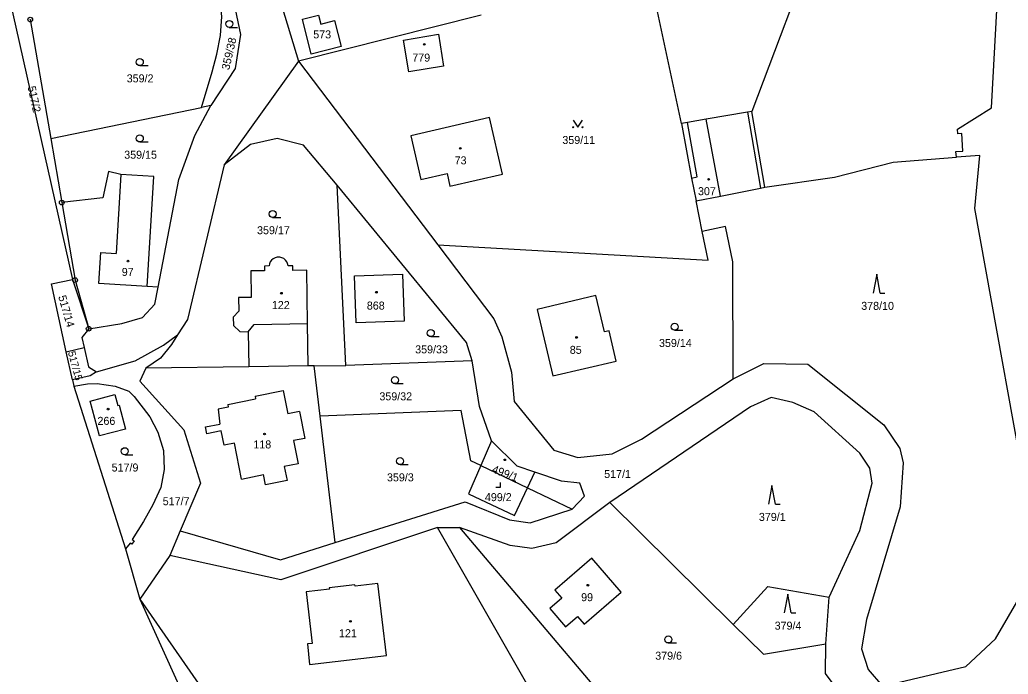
# Model space of a CAD drawing. Extents: x -725728 to -720881, y -1068679 to -1063504.
# Drawn here: x -723846.7 to -723636.7, y -1067162.6 to -1067023.6 of the extents above; entities that cross this region are included whole.
import ezdxf

# ---------------------------------------------------------------- set-up
doc = ezdxf.new("R2010")
doc.units = 0
for name, color, linetype in [('Hranice parcel', 7, 'Continuous'), ('Parcelní čísla', 7, 'Continuous'), ('Vnitřní kresba', 7, 'Continuous'), ('Značky bodu BP', 7, 'Continuous'), ('Značky budov', 7, 'Continuous'), ('Značky kultur', 7, 'Continuous')]:
    doc.layers.add(name, color=color, linetype=linetype)

# ---------------------------------------------------------------- blocks, each defined once
blk = doc.blocks.new('4.02_3')
at = {"layer": 'Značky budov'}
blk.add_circle((-0.001, 0), 0.0175, dxfattribs=at)
blk = doc.blocks.new('4.02_4')
at = {"layer": 'Značky budov'}
blk.add_circle((-0.001, 0), 0.0175, dxfattribs=at)
blk = doc.blocks.new('3.04_2')
at = {"layer": 'Značky kultur'}
blk.add_line((0.001, 0), (0.176, 0), dxfattribs=at)
blk.add_circle((0.001, 0.075), 0.075, dxfattribs=at)
blk = doc.blocks.new('3.14_1')
at = {"layer": 'Značky kultur'}
blk.add_lwpolyline([(-0.1, 0.15), (0, 0), (0.1, 0.15)], dxfattribs=at)
for centre in [(-0.1, 0), (0.1, 0)]:
    blk.add_circle(centre, 0.01, dxfattribs=at)
blk = doc.blocks.new('3.19_2')
at = {"layer": 'Značky kultur'}
for p, q in [((0, 0), (0, 0.1)), ((-0.1, 0), (0, 0))]:
    blk.add_line(p, q, dxfattribs=at)
blk = doc.blocks.new('3.04_3')
at = {"layer": 'Značky kultur'}
blk.add_line((0.001, 0), (0.176, 0), dxfattribs=at)
blk.add_circle((0.001, 0.075), 0.075, dxfattribs=at)
blk = doc.blocks.new('3.08_2')
at = {"layer": 'Značky kultur'}
for p, q in [((0, 0.4), (-0.075, 0)), ((0.075, 0), (0, 0.4)), ((0.075, 0), (0.175, 0))]:
    blk.add_line(p, q, dxfattribs=at)
blk = doc.blocks.new('3.08_1')
at = {"layer": 'Značky kultur'}
for p, q in [((0, 0.4), (-0.075, 0)), ((0.075, 0), (0, 0.4)), ((0.075, 0), (0.175, 0))]:
    blk.add_line(p, q, dxfattribs=at)
blk = doc.blocks.new('1.05_1')
at = {"layer": 'Značky bodu BP'}
for radius in [0.05, 0.00303]:
    blk.add_circle((0, 0), radius, dxfattribs=at)
blk = doc.blocks.new('1.05_2')
at = {"layer": 'Značky bodu BP'}
for radius in [0.05, 0.00303]:
    blk.add_circle((0, 0), radius, dxfattribs=at)

msp = doc.modelspace()

# ---------------------------------------------------------------- linework, layer by layer
at = {"layer": 'Hranice parcel'}
for p, q in [((-723800.5, -1066989.58), (-723787.47, -1067032.44)), ((-723853.97, -1066996.11), (-723835.5, -1067078.81)), ((-723706.12, -1067045.67), (-723712.63, -1067015.3)), ((-723844.43, -1067023.6), (-723840.08, -1067048.83)), ((-723748.64, -1067022.64), (-723787.47, -1067032.44)), ((-723787.47, -1067032.44), (-723803.22, -1067054.44)), ((-723787.47, -1067032.44), (-723757.84, -1067071.43)), ((-723808.1, -1067042.28), (-723805.79, -1067034.69)), ((-723840.08, -1067048.83), (-723808.1, -1067042.28)), ((-723806.11, -1067041.87), (-723808.1, -1067042.28)), ((-723688.38, -1067059.21), (-723691.15, -1067043.09)), ((-723840.08, -1067048.83), (-723837.74, -1067062.44)), ((-723777.4, -1067097.06), (-723779.24, -1067058.73)), ((-723701.71, -1067068.57), (-723703, -1067062.1)), ((-723835.5, -1067078.81), (-723832.03, -1067089.24)), ((-723836.81, -1067094.13), (-723832.97, -1067093.25)), ((-723835.5, -1067100.11), (-723836.81, -1067094.13)), ((-723750.59, -1067096.03), (-723777.4, -1067097.06)), ((-723798.04, -1067097.31), (-723819.87, -1067097.59)), ((-723785.44, -1067097.14), (-723798.04, -1067097.31)), ((-723784.14, -1067097.13), (-723785.44, -1067097.14)), ((-723784.14, -1067097.13), (-723777.4, -1067097.06)), ((-723782.88, -1067107.8), (-723784.14, -1067097.13)), ((-723835.5, -1067100.11), (-723835.21, -1067101.46)), ((-723835.21, -1067101.46), (-723824.2, -1067135.97)), ((-723779.7, -1067134.64), (-723782.88, -1067107.8)), ((-723746.47, -1067113.07), (-723748.74, -1067118.28)), ((-723748.74, -1067118.28), (-723738.81, -1067123.02)), ((-723738.81, -1067123.02), (-723729.37, -1067127.53)), ((-723721.37, -1067126.15), (-723695.13, -1067152.04)), ((-723757.97, -1067131.47), (-723753.26, -1067131.47)), ((-723753.26, -1067131.47), (-723711.52, -1067180.66)), ((-723812.6, -1067132.13), (-723814.76, -1067137.39)), ((-723824.2, -1067135.97), (-723821.14, -1067146.66)), ((-723814.76, -1067137.39), (-723821.14, -1067146.66)), ((-723675.44, -1067156.14), (-723674.75, -1067146.21))]:
    msp.add_line(p, q, dxfattribs=at)
for points in [[(-723647.7, -1067052.84), (-723647.87, -1067051.63), (-723646.38, -1067051.55), (-723646.55, -1067047.78), (-723647.4, -1067047.83), (-723647.51, -1067046.88), (-723640.3, -1067042.37), (-723639.1, -1067020.3), (-723637.58, -1067014.21), (-723655.4, -1066973.45), (-723660.95, -1066965.94), (-723672.9, -1066961.27), (-723681.77, -1066961.89)], [(-723681.77, -1066961.89), (-723676.97, -1067005.41), (-723691.15, -1067043.09)], [(-723802.02, -1067015.94), (-723799.77, -1067026.78), (-723800.89, -1067033.97), (-723806.11, -1067041.87)], [(-723805.79, -1067034.69), (-723804.79, -1067030.91), (-723804.01, -1067026.98), (-723803.77, -1067022.93), (-723804.11, -1067019.8)], [(-723784.76, -1067030.93), (-723786.63, -1067023.51), (-723783.19, -1067022.64), (-723782.71, -1067024.55), (-723779.8, -1067023.82), (-723778.41, -1067029.33), (-723784.76, -1067030.93)], [(-723757.74, -1067026.7), (-723756.63, -1067033.49), (-723764.02, -1067034.68), (-723765.16, -1067027.95), (-723757.74, -1067026.7)], [(-723817.25, -1067080.38), (-723812.87, -1067057.52), (-723809.49, -1067048.21), (-723806.11, -1067041.87)], [(-723691.15, -1067043.09), (-723692.12, -1067043.26), (-723700.86, -1067044.76), (-723704.82, -1067045.44), (-723706.12, -1067045.67)], [(-723746.9, -1067044.41), (-723763.61, -1067048.28), (-723761.48, -1067057.58), (-723755.92, -1067056.31), (-723755.3, -1067058.98), (-723744.12, -1067056.39), (-723746.9, -1067044.41)], [(-723706.12, -1067045.67), (-723703.98, -1067057.25), (-723703, -1067062.1)], [(-723779.24, -1067058.73), (-723786.42, -1067050.24), (-723791.99, -1067048.87), (-723797.65, -1067050.15), (-723803.22, -1067054.44)], [(-723695.14, -1067099.85), (-723688.66, -1067096.62), (-723679.3, -1067096.73), (-723663.12, -1067109.67), (-723659.76, -1067114.67), (-723659, -1067117.71), (-723659.64, -1067127.06), (-723666.81, -1067150.97), (-723667.9, -1067157.17), (-723666.49, -1067161.62), (-723663.45, -1067165.1), (-723645.73, -1067160.97), (-723639.43, -1067155.1), (-723630.63, -1067139.99), (-723630.85, -1067135.32), (-723643.84, -1067063.73), (-723642.77, -1067052.46), (-723647.7, -1067052.84)], [(-723688.38, -1067059.21), (-723673.6, -1067057.08), (-723661.15, -1067053.88), (-723647.7, -1067052.84)], [(-723817.25, -1067080.38), (-723819.62, -1067080.24), (-723818.2, -1067056.89), (-723825.18, -1067056.47), (-723827.83, -1067055.83), (-723829.03, -1067061.41), (-723837.74, -1067062.44)], [(-723803.22, -1067054.44), (-723811.04, -1067087.28), (-723813.14, -1067090.54)], [(-723750.59, -1067096.03), (-723751.8, -1067092.14), (-723779.24, -1067058.73)], [(-723703, -1067062.1), (-723697.83, -1067061.08), (-723689.35, -1067059.38), (-723688.38, -1067059.21)], [(-723837.74, -1067062.44), (-723834.9, -1067078.92), (-723832.03, -1067089.24)], [(-723757.84, -1067071.43), (-723700.48, -1067074.7), (-723701.71, -1067068.57)], [(-723695.14, -1067099.85), (-723695.24, -1067075.04), (-723696.79, -1067067.55), (-723701.71, -1067068.57)], [(-723757.84, -1067071.43), (-723746, -1067087.1), (-723744.25, -1067090.99), (-723742.21, -1067098.48), (-723741.63, -1067104.71), (-723733.26, -1067115.02), (-723728.11, -1067116.58), (-723720.82, -1067115.8), (-723714.59, -1067112.69), (-723695.14, -1067099.85)], [(-723789.68, -1067075.85), (-723789.77, -1067075.41), (-723789.96, -1067075), (-723790.23, -1067074.65), (-723790.58, -1067074.36), (-723790.98, -1067074.16), (-723791.42, -1067074.05), (-723791.57, -1067074.03), (-723792.02, -1067074.06), (-723792.45, -1067074.18), (-723792.85, -1067074.39), (-723793.18, -1067074.69), (-723793.45, -1067075.05), (-723793.62, -1067075.47), (-723793.7, -1067075.91)], [(-723793.7, -1067075.91), (-723794.7, -1067075.92), (-723794.69, -1067076.92), (-723797.59, -1067076.96), (-723797.52, -1067082.58), (-723800.23, -1067082.61), (-723800.11, -1067085.53), (-723801.32, -1067086.75), (-723801.27, -1067088.55), (-723799.94, -1067089.81), (-723798.18, -1067089.86), (-723798.04, -1067097.31)], [(-723785.44, -1067097.14), (-723785.56, -1067088.14), (-723785.71, -1067076.8), (-723788.67, -1067076.84), (-723788.69, -1067075.86), (-723789.68, -1067075.85)], [(-723836.81, -1067094.13), (-723839.96, -1067079.68), (-723835.5, -1067078.81)], [(-723765.04, -1067087.6), (-723775.22, -1067087.95), (-723775.6, -1067077.99), (-723765.39, -1067077.66), (-723765.04, -1067087.6)], [(-723832.03, -1067089.24), (-723824.99, -1067088.11), (-723820.62, -1067086.85), (-723817.95, -1067084.03), (-723817.25, -1067080.38)], [(-723733.42, -1067099.27), (-723719.99, -1067096.09), (-723721.51, -1067089.67), (-723722.48, -1067089.9), (-723724.3, -1067082.21), (-723736.76, -1067085.16), (-723733.42, -1067099.27)], [(-723832.03, -1067089.24), (-723833.45, -1067091.09), (-723832.97, -1067093.25)], [(-723830.34, -1067098.42), (-723822.15, -1067096.07), (-723816.17, -1067092.72), (-723813.14, -1067090.54)], [(-723813.14, -1067090.54), (-723814.45, -1067092.56), (-723816.8, -1067095.49), (-723819.87, -1067097.59)], [(-723832.97, -1067093.25), (-723832.06, -1067097.32), (-723830.34, -1067098.42)], [(-723746.47, -1067113.07), (-723749.01, -1067105.74), (-723750.59, -1067096.03)], [(-723819.87, -1067097.59), (-723821.19, -1067100.37), (-723811.82, -1067110.73), (-723808.3, -1067122.06), (-723812.6, -1067132.13)], [(-723830.34, -1067098.42), (-723831.7, -1067099.22), (-723835.5, -1067100.11)], [(-723835.21, -1067101.46), (-723832.27, -1067100.93), (-723830.2, -1067100.83), (-723826.4, -1067101.4), (-723823.47, -1067102.47), (-723822.39, -1067103.65), (-723819.06, -1067107.94), (-723817.32, -1067111.2), (-723816.14, -1067115.07), (-723815.99, -1067119.11), (-723816.7, -1067122.95), (-723818.42, -1067126.65), (-723820.4, -1067130.13), (-723822.79, -1067133.99), (-723822.37, -1067134.25), (-723822.83, -1067135), (-723823.25, -1067134.74), (-723824.2, -1067135.97)], [(-723824.19, -1067110.54), (-723829.74, -1067112), (-723831.69, -1067104.6), (-723826.46, -1067103.22), (-723825.85, -1067105.53), (-723825.55, -1067105.46), (-723824.19, -1067110.54)], [(-723674.75, -1067146.21), (-723668.22, -1067132.08), (-723665.64, -1067122.05), (-723666.09, -1067118.86), (-723668.22, -1067115.67), (-723677.94, -1067106.86), (-723682.49, -1067104.88), (-723687.05, -1067103.82), (-723691.45, -1067105.79), (-723721.37, -1067126.15)], [(-723748.74, -1067118.28), (-723750.86, -1067117.27), (-723752.91, -1067106.62), (-723782.88, -1067107.8)], [(-723729.37, -1067127.53), (-723726.73, -1067124.79), (-723727.71, -1067122.06), (-723731.62, -1067121.57), (-723737.24, -1067119.69), (-723741, -1067118.44), (-723746.47, -1067113.07)], [(-723748.74, -1067118.28), (-723751.35, -1067124.3), (-723741.58, -1067128.9), (-723738.81, -1067123.02)], [(-723779.7, -1067134.64), (-723752.03, -1067125.97), (-723742.66, -1067129.78), (-723738.26, -1067130.46), (-723729.37, -1067127.53)], [(-723721.37, -1067126.15), (-723732.76, -1067134.66), (-723737.92, -1067135.88), (-723742.48, -1067135.27), (-723753.26, -1067131.47)], [(-723757.97, -1067131.47), (-723791.23, -1067142.56), (-723814.76, -1067137.39)], [(-723794.02, -1067190.01), (-723729.6, -1067180.98), (-723757.97, -1067131.47)], [(-723812.6, -1067132.13), (-723791.3, -1067138.28), (-723779.7, -1067134.64)], [(-723731.55, -1067146.44), (-723734.09, -1067148.62), (-723730.74, -1067152.53), (-723728.19, -1067150.35), (-723726.82, -1067151.94), (-723718.94, -1067145.18), (-723725.14, -1067137.96), (-723733.02, -1067144.72), (-723731.55, -1067146.44)], [(-723768.79, -1067158.62), (-723770.58, -1067143.32), (-723775.44, -1067143.89), (-723775.48, -1067143.59), (-723780.94, -1067144.24), (-723780.91, -1067144.53), (-723785.82, -1067145.11), (-723784.54, -1067156.04), (-723785.53, -1067156.15), (-723785.13, -1067160.53), (-723768.79, -1067158.62)], [(-723695.13, -1067152.04), (-723687.81, -1067143.93), (-723674.75, -1067146.21)], [(-723821.14, -1067146.66), (-723810.82, -1067169.45), (-723797.29, -1067190.49), (-723792.14, -1067202.88), (-723787.13, -1067202.72)], [(-723821.14, -1067146.66), (-723804.59, -1067170.51), (-723794.02, -1067190.01)], [(-723695.13, -1067152.04), (-723688.72, -1067158.36), (-723675.44, -1067156.14)], [(-723672.5, -1067166.55), (-723675.51, -1067162.46), (-723675.44, -1067156.14)]]:
    msp.add_lwpolyline(points, dxfattribs=at)
at = {"layer": 'Vnitřní kresba'}
for p, q in [((-723692.12, -1067043.26), (-723689.35, -1067059.38)), ((-723702.81, -1067057), (-723704.82, -1067045.44)), ((-723697.83, -1067061.08), (-723700.86, -1067044.76)), ((-723825.18, -1067056.47), (-723826.2, -1067073.24)), ((-723703.98, -1067057.25), (-723702.81, -1067057)), ((-723829.84, -1067079.62), (-723829.44, -1067073.04)), ((-723829.44, -1067073.04), (-723826.2, -1067073.24)), ((-723819.62, -1067080.24), (-723829.84, -1067079.62)), ((-723798.18, -1067089.86), (-723796.85, -1067088.32)), ((-723796.85, -1067088.32), (-723785.56, -1067088.14)), ((-723796.69, -1067103.53), (-723790.71, -1067102.32)), ((-723790.71, -1067102.32), (-723789.7, -1067107.32)), ((-723802.5, -1067105.32), (-723796.57, -1067104.12)), ((-723796.69, -1067103.53), (-723796.57, -1067104.12)), ((-723802.38, -1067105.89), (-723804.49, -1067106.31)), ((-723804.49, -1067106.31), (-723804.15, -1067109.48)), ((-723802.5, -1067105.32), (-723802.38, -1067105.89)), ((-723787.25, -1067106.82), (-723789.7, -1067107.32)), ((-723787.25, -1067106.82), (-723786.1, -1067112.51)), ((-723807.24, -1067110.1), (-723804.15, -1067109.48)), ((-723806.95, -1067111.52), (-723807.24, -1067110.1)), ((-723803.87, -1067110.9), (-723806.95, -1067111.52)), ((-723803.24, -1067113.99), (-723803.87, -1067110.9)), ((-723786.1, -1067112.51), (-723788.55, -1067113)), ((-723801.09, -1067113.55), (-723803.24, -1067113.99)), ((-723799.55, -1067121.15), (-723801.09, -1067113.55)), ((-723788.55, -1067113), (-723787.55, -1067117.91)), ((-723787.55, -1067117.91), (-723790.5, -1067118.5)), ((-723790.5, -1067118.5), (-723789.9, -1067121.44)), ((-723799.55, -1067121.15), (-723794.89, -1067120.21)), ((-723794.46, -1067122.36), (-723794.89, -1067120.21)), ((-723738.81, -1067123.02), (-723737.24, -1067119.69)), ((-723789.9, -1067121.44), (-723794.46, -1067122.36))]:
    msp.add_line(p, q, dxfattribs=at)

# ---------------------------------------------------------------- block references
at = {"layer": 'Značky bodu BP', "xscale": 10, "yscale": 10}
for name, p in [('1.05_1', (-723844.43, -1067023.6)), ('1.05_1', (-723837.74, -1067062.44)), ('1.05_2', (-723834.9, -1067078.92)), ('1.05_1', (-723832.03, -1067089.24))]:
    msp.add_blockref(name, p, dxfattribs=at)
at = {"layer": 'Značky budov', "xscale": 10, "yscale": 10}
for name, p in [('4.02_3', (-723760.73, -1067028.87)), ('4.02_3', (-723753.08, -1067050.95)), ('4.02_3', (-723700.35, -1067057.5)), ('4.02_4', (-723823.67, -1067074.88)), ('4.02_3', (-723770.89, -1067081.48)), ('4.02_3', (-723791.07, -1067081.69)), ('4.02_3', (-723728.4, -1067091.09)), ('4.02_3', (-723827.89, -1067106.31)), ('4.02_3', (-723794.66, -1067111.6)), ('4.02_3', (-723743.63, -1067117.07)), ('4.02_3', (-723725.99, -1067143.69)), ('4.02_3', (-723776.41, -1067151.35))]:
    msp.add_blockref(name, p, dxfattribs=at)
at = {"layer": 'Značky kultur', "xscale": 10, "yscale": 10}
for name, p in [('3.04_2', (-723802.17, -1067025.27)), ('3.04_3', (-723821.18, -1067033.38)), ('3.14_1', (-723728.11, -1067046.46)), ('3.04_2', (-723821.18, -1067049.59)), ('3.04_2', (-723792.96, -1067065.62)), ('3.08_2', (-723664.64, -1067081.68)), ('3.04_3', (-723759.38, -1067090.92)), ('3.04_2', (-723707.59, -1067089.56)), ('3.04_3', (-723766.98, -1067100.89)), ('3.04_2', (-723824.38, -1067116)), ('3.04_2', (-723765.9, -1067118.09)), ('3.19_2', (-723744.58, -1067122.89)), ('3.08_1', (-723686.9, -1067126.49)), ('3.08_1', (-723683.56, -1067149.58)), ('3.04_2', (-723708.92, -1067155.96))]:
    msp.add_blockref(name, p, dxfattribs=at)

# ---------------------------------------------------------------- texts
at = {"layer": 'Parcelní čísla'}
for s, p in [('573', (-723784.33, -1067027.59)), ('779', (-723763.29, -1067032.52)), ('359/2', (-723823.95, -1067036.93)), ('359/11', (-723731.42, -1067050.01)), ('359/15', (-723824.48, -1067053.14)), ('73', (-723754.3, -1067054.34)), ('307', (-723702.61, -1067060.88)), ('359/17', (-723796.26, -1067069.17)), ('97', (-723825, -1067078.03)), ('122', (-723793.12, -1067085.06)), ('868', (-723772.95, -1067085.17)), ('378/10', (-723667.94, -1067085.23)), ('359/14', (-723710.89, -1067093.11)), ('359/33', (-723762.68, -1067094.47)), ('85', (-723729.84, -1067094.57)), ('359/32', (-723770.28, -1067104.44)), ('266', (-723830.16, -1067109.65)), ('118', (-723797.05, -1067114.65)), ('517/9', (-723827.15, -1067119.55)), ('517/1', (-723722.54, -1067120.93)), ('359/3', (-723768.67, -1067121.64)), ('517/7', (-723816.3, -1067126.71)), ('499/2', (-723747.87, -1067125.84)), ('379/1', (-723689.67, -1067130.04)), ('99', (-723727.43, -1067147.08)), ('379/4', (-723686.33, -1067153.13)), ('121', (-723778.86, -1067154.73)), ('379/6', (-723711.69, -1067159.51))]:
    msp.add_text(s, height=1.7, dxfattribs=at).set_placement(p)
for s, height, rotation, p in [('359/38', 1.7, 77, (-723802.18, -1067034.4)), ('517/2', 1.7, 282, (-723845, -1067037.89)), ('517/14', 1.7, 286, (-723838.52, -1067082.4)), ('517/15', 1.552, 285, (-723836.44, -1067094.23)), ('499/1', 1.7, 339, (-723746.52, -1067119.71))]:
    msp.add_text(s, height=height, rotation=rotation, dxfattribs=at).set_placement(p)

doc.saveas('drawing.dxf')
